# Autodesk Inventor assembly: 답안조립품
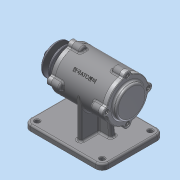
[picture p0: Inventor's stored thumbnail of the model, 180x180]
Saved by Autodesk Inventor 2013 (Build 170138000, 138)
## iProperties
Created: 2015-12
Part Number: 답안조립품
Document SubType Name: Assembly
Designer: dgall
Author: dgall
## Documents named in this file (11)
- C:\Users\dgall\Desktop\451207V1018\답안조립품.iam
- C:\Users\dgall\Desktop\451207V1018\본체.ipt
- C:\Users\dgall\Desktop\451207V1018\451207V1018\V-벨트풀리.ipt
- C:\Users\dgall\Desktop\451207V1018\451207V1018\너트 M12x1.25.ipt
- C:\Users\dgall\Desktop\451207V1018\451207V1018\베어링 6204.ipt
- C:\Users\dgall\Desktop\451207V1018\451207V1018\볼트 M4 x 12.ipt
- C:\Users\dgall\Desktop\451207V1018\451207V1018\오일실.ipt
- C:\Users\dgall\Desktop\451207V1018\451207V1018\축.ipt
- C:\Users\dgall\Desktop\451207V1018\451207V1018\커버.ipt
- C:\Users\dgall\Desktop\451207V1018\451207V1018\커버2.ipt
- C:\Users\dgall\Desktop\451207V1018\451207V1018\키(4 x 4 x 12).ipt
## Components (6 placed, 5 different names)
1. V-벨트풀리:1
2. KS B 1012 클래스 1 일반 - 미터 M12x1.25:1
3. KS B 2023 6204 - 20 x 47 x 14:1
4. KS B 2804 D D - 20 32 8:1
5. KS B 1311 (I) 4 x 4 x 12:1
6. KS B 2023 6204 - 20 x 47 x 14:2
